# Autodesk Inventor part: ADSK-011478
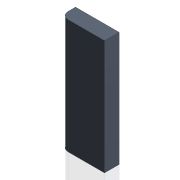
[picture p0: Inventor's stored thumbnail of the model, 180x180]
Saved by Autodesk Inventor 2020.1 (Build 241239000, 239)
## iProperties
Created: 2000-01
Part Number: ADSK-011478
Description: PLT-02,SN,CP,05,015,040,BLOCK,SPACER
Document SubType Name: Modeling
Designer: sspink
Material: Pearson Nylatron
Density: 1.13867 g/cm^3
Appearance: Nylatron
Mass: 53.739 g
Surface Area: 110.583 cm^2
Volume: 47.1945 cm^3
Control State: 0
Checked Out: False
Master: False
Shininess: 10.0
Length Units: 11269
Angle Units: 11279
Time Units: 11290
Mass Units: 11283
Length Display Precision: 3
Angle Display Precision: 2
Compacted: True
Cutlength: 1.50 X 4.00 (6 SI)
Material Desc: SHEET,NYLATRON,0.500
Material_number: A081543
Dimensions: 38x100x12,7 mm
Mass: 0,054 kg
DocNumber: ADSK-011478.ipt
Folder: 01 - Themengebiete\Simplification\01 - Packaging machine\
VDS_Category: 3D Komponenten
Density: 1.13867
Volumn: 48.03735621173677
Area: 112.37337083863524
PropertySet Name: Model Information
Author: sspink
Revision Number: -
Title: PLT-02,SN,CP,05,015,040,BLOCK,SPACER
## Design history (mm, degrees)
node "Solide1"
  node "Extrusion1" dims "d6" = 12.7, "d7" = 0
  node "Hole1" dims "d13" = 3.242, "d14" = 9.525, "d15" = 6.35, "d16" = 60 deg, "d17" = 11.8, "d18" = 118 deg, "d22" = 8
  node "Fillet2" dims "d19" = 6.35
sketch "Sketch1"
  geometry: L1 (-19, -50)-(-19, 50); L2 (-19, -50)-(19, -50); L3 (-19, 50)-(19, 50); L4 (19, 50)-(19, -50); 3 further points
  constraints: 8 end point, 2 midpoint, 2 perpendicular, 1 horizontal alignment, 1 parallel, 1 vertical, 1 vertical alignment
  dimensions: "d2" = 100 distance between parallel lines of L3 L2; "d5" = 38 distance of L1.start L2.end
sketch "Sketch2"
  geometry: L1 (19, 50)-(19, -50) reference; L2 (9.5, 31.75)-(9.5, -31.75); 2 further points
  constraints: 2 end point, 2 midpoint, 1 horizontal alignment, 1 vertical
  dimensions: "d20" = 9.5 distance between parallel lines of L1 L2; "d21" = 63.5 distance of L2.start L2.end
node "Corps solides"
node "Corps surfaciques"
